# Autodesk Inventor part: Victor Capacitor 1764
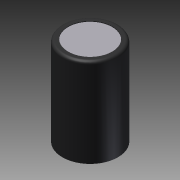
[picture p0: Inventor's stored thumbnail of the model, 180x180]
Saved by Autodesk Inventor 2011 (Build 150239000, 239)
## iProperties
Shininess: 64.0
Length Units: 11272
Angle Units: 11279
Time Units: 11290
Mass Units: 11286
Length Display Precision: 3
Angle Display Precision: 2
Compacted: True
Part Number: Victor Capacitor 1764
Document SubType Name: Modeling
Created: 2007-01
Designer: uidk0133
Density: 1 g/cm^3
Density: 0.0
Volumn: 0.0
Area: 0.0
PropertySet Name: Model Information
Control State: 0
Master: False
Checked Out: False
Author: uidk0133
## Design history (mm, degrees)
sketch "Sketch1"
  geometry: C1 r 6.35 at (0, 0)
  constraints: 1 centre point
  dimensions: "d0" = 12.7 diameter of C1
extrude "Extrusion1" new body sketch "Sketch1" stored distance "d1" = 20.32; taper "d2" = 0 deg
fillet "Fillet1" dims "d3" = 0.635
sketch "Sketch2"
  geometry: C1 r 5.715 at (0, 0) reference; C2 r 5.035 at (0, 0)
  constraints: 1 centre point, 1 coincident, 1 concentric
extrude "Extrusion2" cut sketch "Sketch2" distance "d4" = 0.127; taper "d5" = 0 deg
body "Solid1"
